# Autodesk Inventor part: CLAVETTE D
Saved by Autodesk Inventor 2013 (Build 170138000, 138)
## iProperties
Created: 2012-12
Part Number: CLAVETTE D
Material: Générique
Document SubType Name: Modeling
Designer: jost thierry
Density: 1 g/cm^3
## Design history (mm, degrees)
node "CLAVETTE D1"
node "CLAVETTE D"
node "Base1"
